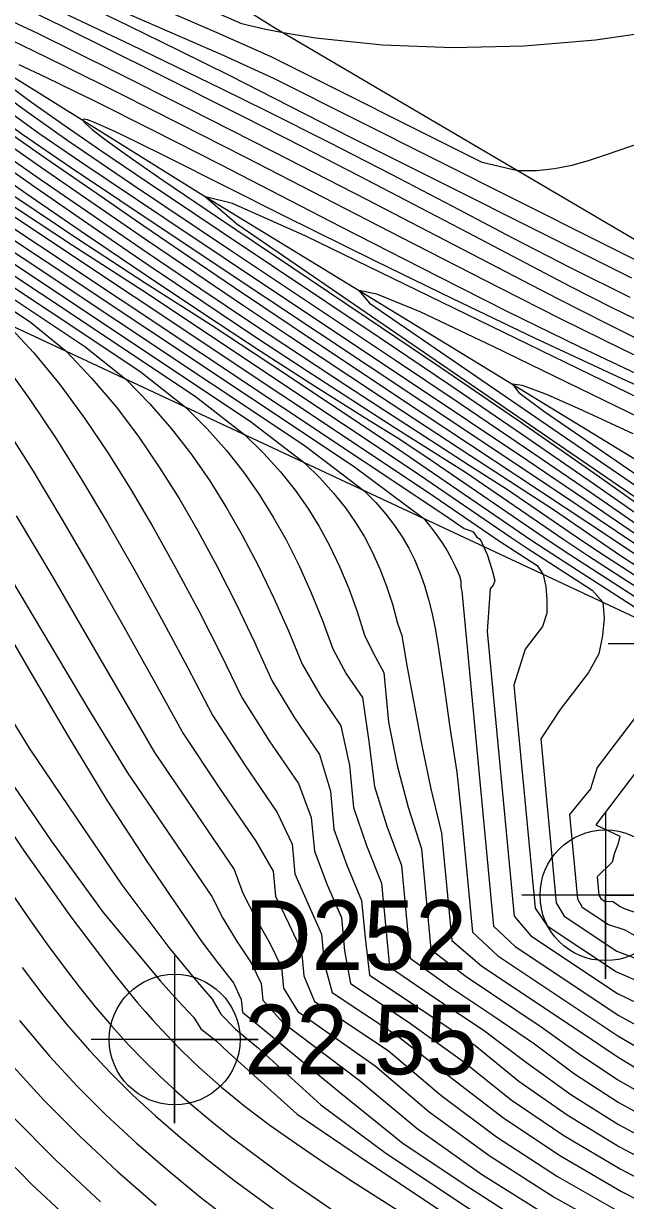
# Model space of a CAD drawing. Extents: x 2356077 to 2359823, y 225951 to 227822.
# Drawn here: x 2356709.45 to 2356731.04, y 227178.59 to 227220.81 of the extents above; entities that cross this region are included whole.
import ezdxf

# ---------------------------------------------------------------- set-up
doc = ezdxf.new("R2010")
doc.units = 0
for name, color, linetype in [('DTM Contours Major', 7, 'Continuous'), ('DTM Contours Minor', 7, 'Continuous'), ('Exist DTM Breakline', 7, 'Continuous'), ('Exist DTM Breakline Cogo Point CELL', 7, 'Continuous'), ('Exist DTM Regular Point CELL', 7, 'Continuous'), ('Exist DTM Regular Point Cogo Elevation', 7, 'Continuous'), ('Exist DTM Regular Point Cogo Number', 7, 'Continuous'), ('PH Exist DTM Breakline', 7, 'Continuous')]:
    doc.layers.add(name, color=color, linetype=linetype)

msp = doc.modelspace()

# ---------------------------------------------------------------- linework, layer by layer
at = {"layer": 'DTM Contours Major'}
for points in [[(2356697.999, 227222.074), (2356700.071, 227220.561), (2356702.169, 227219.049), (2356704.302, 227217.538), (2356706.479, 227216.026), (2356708.707, 227214.512), (2356711.208, 227212.858), (2356713.724, 227211.231), (2356720.925, 227206.443), (2356723.392, 227204.798), (2356726.934, 227202.371), (2356727.516, 227201.988), (2356729.842, 227200.486), (2356730.232, 227200.051), (2356730.279, 227199.475), (2356730.221, 227198.856), (2356730.084, 227198.2), (2356729.708, 227197.527), (2356728.702, 227196.203), (2356728, 227195.153), (2356728.559, 227189.267), (2356728.844, 227188.788), (2356730.726, 227187.535), (2356731.553, 227187.225)], [(2356701.503, 227221.717), (2356704.421, 227219.635), (2356707.31, 227217.594), (2356710.099, 227215.646), (2356712.021, 227214.316), (2356713.861, 227213.055), (2356715.63, 227211.853), (2356717.336, 227210.702), (2356718.989, 227209.596), (2356722.257, 227207.428), (2356725.455, 227205.328), (2356728.492, 227203.35), (2356730.025, 227202.3), (2356730.902, 227201.71), (2356734.234, 227199.558)], [(2356731.267, 227211.674), (2356721.187, 227216.729), (2356716.858, 227218.937), (2356715.043, 227219.84), (2356713.244, 227220.717), (2356711.454, 227221.577)], [(2356732.139, 227207.909), (2356729.416, 227209.203), (2356726.802, 227210.488), (2356724.323, 227211.735), (2356720.827, 227213.526), (2356716.529, 227215.742), (2356714.08, 227216.991), (2356711.989, 227218.037), (2356711.314, 227218.369), (2356710.265, 227218.878), (2356709.298, 227219.333)], [(2356708.714, 227218.744), (2356709.738, 227217.997), (2356710.944, 227217.147), (2356712.264, 227216.235), (2356713.887, 227215.131), (2356716.461, 227213.4), (2356722.201, 227209.559), (2356724.737, 227207.85), (2356727.311, 227206.098), (2356729.898, 227204.314), (2356732.471, 227202.508)], [(2356705.312, 227214.713), (2356717.581, 227206.554), (2356719.533, 227205.053), (2356720.087, 227204.502), (2356720.571, 227203.967), (2356720.993, 227203.441), (2356721.36, 227202.919), (2356721.679, 227202.394), (2356721.959, 227201.861), (2356722.231, 227201.255), (2356722.468, 227200.629), (2356722.678, 227199.978), (2356722.864, 227199.299), (2356723.024, 227198.862), (2356723.188, 227197.841), (2356723.733, 227194.91), (2356724.063, 227193.356), (2356724.444, 227191.77), (2356724.81, 227187.914), (2356725.885, 227186.997), (2356729.504, 227184.589), (2356730.775, 227183.728), (2356732.141, 227182.907)], [(2356708.834, 227210.055), (2356709.817, 227208.995), (2356710.749, 227207.859), (2356711.637, 227206.657), (2356712.486, 227205.399), (2356713.301, 227204.097), (2356714.088, 227202.759), (2356714.93, 227201.253), (2356715.744, 227199.725), (2356716.528, 227198.184), (2356717.282, 227196.637), (2356718.264, 227195.08), (2356719.31, 227193.547), (2356719.769, 227192.329), (2356719.884, 227191.118), (2356720.345, 227189.92), (2356720.854, 227188.744), (2356720.967, 227187.552), (2356721.181, 227186.369), (2356723.247, 227184.994), (2356725.239, 227183.562), (2356726.945, 227182.205), (2356728.824, 227180.923), (2356730.855, 227179.72), (2356733.018, 227178.595)], [(2356706.808, 227202.53), (2356709.623, 227197.665), (2356711.028, 227195.278), (2356712.439, 227192.956), (2356713.907, 227190.705), (2356715.848, 227187.864), (2356716.404, 227187.126), (2356716.976, 227186.404), (2356717.257, 227185.795), (2356717.3, 227185.341), (2356718.31, 227184.52), (2356720.825, 227182.44), (2356723.072, 227180.635), (2356725.493, 227179.017), (2356728.202, 227177.269)], [(2356709.402, 227186.951), (2356710.18, 227185.922), (2356710.979, 227184.93), (2356711.81, 227183.975), (2356712.566, 227183.171), (2356713.359, 227182.386), (2356714.194, 227181.615), (2356715.075, 227180.85), (2356716.007, 227180.086), (2356716.996, 227179.317), (2356719.032, 227177.826)]]:
    msp.add_lwpolyline(points, dxfattribs=at)
at = {"layer": 'DTM Contours Minor'}
for points in [[(2356675.565, 227239.487), (2356688.723, 227229.4), (2356689.261, 227228.93), (2356690.65, 227227.923), (2356691.684, 227227.129), (2356692.88, 227226.225), (2356697.895, 227222.574), (2356700.14, 227220.945), (2356702.376, 227219.334), (2356704.613, 227217.742), (2356706.862, 227216.167), (2356709.134, 227214.608), (2356711.469, 227213.044), (2356713.813, 227211.513), (2356716.138, 227210.032), (2356718.323, 227208.596), (2356722.824, 227205.597), (2356727.68, 227202.269), (2356729.317, 227201.207), (2356731.77, 227199.622)], [(2356675.054, 227229.772), (2356678.521, 227226.89), (2356681.448, 227223.752), (2356684.011, 227220.483), (2356688.753, 227214.079), (2356690.856, 227211.218), (2356692.64, 227208.461), (2356693.369, 227207.313), (2356694.719, 227205.162), (2356696.577, 227202.16), (2356699.99, 227196.632), (2356701.76, 227193.78), (2356702.834, 227192.065), (2356703.948, 227190.324), (2356705.11, 227188.579), (2356706.328, 227186.85), (2356707.608, 227185.161), (2356708.957, 227183.532), (2356710.191, 227182.178), (2356711.48, 227180.88), (2356712.822, 227179.631), (2356714.211, 227178.427)], [(2356736.072, 227207.936), (2356730.541, 227210.624), (2356729.085, 227211.366), (2356725.372, 227213.321), (2356723.451, 227214.325), (2356721.479, 227215.347), (2356719.453, 227216.388), (2356717.367, 227217.45), (2356714.199, 227219.041), (2356710.847, 227220.708), (2356709.227, 227221.495), (2356707.974, 227222.06), (2356697.238, 227227.105), (2356694.71, 227228.259), (2356694.083, 227228.263), (2356694.08, 227228.231), (2356695.667, 227226.882), (2356709.422, 227216.828), (2356711.101, 227215.687), (2356712.905, 227214.473), (2356716.283, 227212.214), (2356725.551, 227206.057), (2356729.331, 227203.536), (2356732.071, 227201.697)], [(2356732.263, 227209.1), (2356730.435, 227210.012), (2356728.615, 227210.943), (2356721.799, 227214.473), (2356718.415, 227216.212), (2356715.383, 227217.751), (2356712.713, 227219.089), (2356709.958, 227220.456), (2356704.772, 227222.89), (2356700.424, 227224.933), (2356698.91, 227225.553), (2356698.454, 227225.535), (2356699.216, 227224.754), (2356709.996, 227216.878), (2356711.545, 227215.826), (2356714.516, 227213.826), (2356718.739, 227211.009), (2356723.205, 227208.035), (2356725.372, 227206.585), (2356727.498, 227205.157), (2356729.582, 227203.749), (2356731.625, 227202.357)], [(2356732.451, 227220.577), (2356729.965, 227220.213), (2356727.408, 227220), (2356724.842, 227219.941), (2356722.325, 227220.037), (2356719.917, 227220.292), (2356719.334, 227220.381), (2356718.762, 227220.481), (2356718.136, 227220.604), (2356717.521, 227220.741), (2356717.275, 227220.805), (2356707.515, 227225.057)], [(2356732.053, 227216.692), (2356730.351, 227216.098), (2356729.733, 227215.895), (2356729.118, 227215.723), (2356728.494, 227215.597), (2356727.849, 227215.53), (2356727.171, 227215.534), (2356725.896, 227215.824), (2356718.305, 227219.632), (2356716.394, 227220.479), (2356710.754, 227222.935)], [(2356681.237, 227222.134), (2356683.269, 227219.385), (2356685.378, 227216.437), (2356687.487, 227213.416), (2356689.515, 227210.456), (2356691.378, 227207.687), (2356692.59, 227205.86), (2356693.704, 227204.157), (2356694.749, 227202.532), (2356695.464, 227201.406), (2356696.169, 227200.284), (2356697.582, 227198.006), (2356700.266, 227193.63), (2356701.555, 227191.569), (2356702.925, 227189.461), (2356704.38, 227187.347), (2356705.923, 227185.267), (2356707.556, 227183.261), (2356709.051, 227181.605), (2356710.605, 227180.031), (2356712.209, 227178.536)], [(2356701.453, 227222.201), (2356704.401, 227220.096), (2356707.374, 227217.995), (2356710.258, 227215.978), (2356712.051, 227214.737), (2356713.767, 227213.558), (2356715.42, 227212.431), (2356717.019, 227211.348), (2356720.1, 227209.279), (2356723.707, 227206.876), (2356727.175, 227204.58), (2356730.504, 227202.381), (2356731.445, 227201.741)], [(2356700.124, 227221.9), (2356702.572, 227220.132), (2356705.02, 227218.376), (2356707.454, 227216.646), (2356709.858, 227214.956), (2356711.907, 227213.536), (2356713.915, 227212.162), (2356715.875, 227210.837), (2356717.78, 227209.567), (2356719.621, 227208.355), (2356721.392, 227207.205), (2356722.743, 227206.338), (2356725.297, 227204.721), (2356728.829, 227202.3), (2356729.689, 227201.73), (2356733.811, 227199.067)], [(2356733.234, 227208.028), (2356730.946, 227209.122), (2356728.712, 227210.223), (2356726.546, 227211.316), (2356722.996, 227213.136), (2356717.42, 227216.005), (2356715.022, 227217.226), (2356712.962, 227218.263), (2356710.872, 227219.304), (2356709.816, 227219.826), (2356708.234, 227220.588), (2356705.153, 227222.036)], [(2356697.999, 227221.22), (2356699.889, 227219.893), (2356701.823, 227218.568), (2356703.633, 227217.313), (2356705.314, 227216.085), (2356707.087, 227214.8), (2356724.557, 227203.181), (2356725.256, 227202.702), (2356725.466, 227202.625), (2356725.577, 227202.574), (2356725.713, 227202.389), (2356725.823, 227202.317), (2356725.952, 227202.052), (2356726.073, 227201.763), (2356726.18, 227201.463), (2356726.274, 227201.151), (2356726.358, 227200.827), (2356726.289, 227200.662), (2356726.19, 227200.532), (2356726.083, 227198.999), (2356727.053, 227188.795), (2356727.641, 227188.084), (2356730.758, 227186.01), (2356731.847, 227185.485)], [(2356698, 227221.629), (2356699.972, 227220.201), (2356701.983, 227218.769), (2356704.043, 227217.331), (2356706.163, 227215.885), (2356708.144, 227214.52), (2356723.969, 227203.993), (2356726.14, 227202.505), (2356726.49, 227202.269), (2356727.878, 227201.372), (2356728.092, 227201.051), (2356728.18, 227200.62), (2356728.218, 227200.155), (2356728.216, 227199.658), (2356728.065, 227199.183), (2356727.444, 227198.365), (2356727.041, 227197.076), (2356727.801, 227189.077), (2356728.227, 227188.447), (2356730.713, 227186.792), (2356731.661, 227186.387)], [(2356700.189, 227221.392), (2356702.536, 227219.698), (2356704.877, 227218.019), (2356707.21, 227216.362), (2356709.533, 227214.734), (2356711.704, 227213.237), (2356713.845, 227211.783), (2356715.94, 227210.383), (2356717.97, 227209.051), (2356719.916, 227207.798), (2356721.76, 227206.637), (2356722.947, 227205.905), (2356724.112, 227205.123), (2356728.154, 227202.354), (2356729.046, 227201.764), (2356733.341, 227198.989)], [(2356701.486, 227221.269), (2356704.363, 227219.22), (2356707.178, 227217.234), (2356709.889, 227215.342), (2356711.947, 227213.922), (2356713.919, 227212.575), (2356715.811, 227211.294), (2356717.63, 227210.075), (2356719.382, 227208.912), (2356721.073, 227207.799), (2356722.574, 227206.819), (2356724.029, 227205.875), (2356725.439, 227204.969), (2356726.803, 227204.098), (2356729.47, 227202.27), (2356730.32, 227201.704), (2356734.354, 227199.098)], [(2356704.67, 227221.234), (2356709.553, 227217.665), (2356711.004, 227216.639), (2356713.36, 227215.04), (2356716.869, 227212.688), (2356722.753, 227208.76), (2356725.11, 227207.177), (2356727.456, 227205.59), (2356729.782, 227204.002), (2356732.078, 227202.414)], [(2356731.207, 227210.987), (2356729.09, 227212.037), (2356726.999, 227213.113), (2356724.851, 227214.25), (2356722.648, 227215.401), (2356720.415, 227216.547), (2356718.177, 227217.674), (2356716.551, 227218.476), (2356714.927, 227219.265), (2356713.298, 227220.047), (2356709.991, 227221.616)], [(2356733.03, 227211.517), (2356718.451, 227218.83), (2356716.624, 227219.668), (2356713.044, 227221.227)], [(2356711.628, 227177.418), (2356709.751, 227179.169), (2356707.915, 227181.033), (2356706.113, 227182.947), (2356704.202, 227185.43), (2356702.377, 227187.936), (2356700.671, 227190.469), (2356699.086, 227192.96), (2356697.626, 227195.343), (2356695.726, 227198.496), (2356694.648, 227200.26), (2356694.127, 227201.097), (2356693.611, 227201.913), (2356693.092, 227202.717), (2356692.345, 227203.848), (2356691.567, 227204.993), (2356690.742, 227206.177), (2356689.508, 227207.901), (2356688.186, 227209.709), (2356686.804, 227211.567), (2356685.395, 227213.442), (2356682.614, 227217.105), (2356680.51, 227219.871), (2356679.542, 227221.158)], [(2356698.01, 227220.857), (2356699.858, 227219.586), (2356701.518, 227218.393), (2356704.812, 227215.986), (2356706.531, 227214.747), (2356721.277, 227204.941), (2356723.813, 227203.052), (2356724.05, 227202.759), (2356724.266, 227202.469), (2356724.462, 227202.181), (2356724.639, 227201.894), (2356724.799, 227201.607), (2356724.944, 227201.318), (2356725.087, 227200.995), (2356725.129, 227200.826), (2356725.14, 227200.634), (2356725.152, 227200.54), (2356725.17, 227200.447), (2356726.312, 227188.429), (2356727.083, 227187.704), (2356730.802, 227185.229), (2356731.938, 227184.6)], [(2356734.078, 227206.636), (2356730.918, 227208.064), (2356727.815, 227209.513), (2356724.842, 227210.936), (2356722.074, 227212.289), (2356718.79, 227213.921), (2356714.601, 227216.025), (2356713.519, 227216.559), (2356712.728, 227216.938), (2356712.321, 227217.124), (2356711.99, 227217.265), (2356711.747, 227217.354), (2356711.602, 227217.384), (2356711.568, 227217.347), (2356711.67, 227217.223), (2356711.912, 227217.014), (2356712.281, 227216.729), (2356712.764, 227216.376), (2356713.348, 227215.962), (2356714.449, 227215.2), (2356716.407, 227213.871), (2356721.743, 227210.284), (2356724.415, 227208.476), (2356727.165, 227206.597), (2356729.91, 227204.691), (2356732.57, 227202.806)], [(2356702.314, 227215.017), (2356709.686, 227210.114), (2356710.974, 227209.055), (2356711.905, 227208.078), (2356712.767, 227207.058), (2356713.569, 227205.997), (2356714.319, 227204.9), (2356715.026, 227203.771), (2356715.699, 227202.614), (2356716.409, 227201.307), (2356717.088, 227199.974), (2356717.736, 227198.621), (2356718.354, 227197.251), (2356719.167, 227195.907), (2356720.069, 227194.587), (2356720.454, 227193.277), (2356720.584, 227191.913), (2356721.044, 227190.623), (2356721.571, 227189.358), (2356721.699, 227188.011), (2356721.861, 227186.668), (2356725.632, 227184.158), (2356727.216, 227182.871), (2356728.946, 227181.658), (2356730.822, 227180.52), (2356732.827, 227179.457)], [(2356703.064, 227214.941), (2356711.647, 227209.233), (2356713.114, 227208.054), (2356713.976, 227207.172), (2356714.759, 227206.271), (2356715.472, 227205.349), (2356716.126, 227204.408), (2356716.729, 227203.444), (2356717.292, 227202.458), (2356717.878, 227201.342), (2356718.429, 227200.199), (2356718.949, 227199.029), (2356719.441, 227197.834), (2356720.085, 227196.714), (2356720.832, 227195.619), (2356721.142, 227194.199), (2356721.286, 227192.686), (2356721.756, 227191.323), (2356722.287, 227189.98), (2356722.573, 227186.967), (2356724.239, 227185.837), (2356725.93, 227184.712), (2356727.492, 227183.538), (2356729.074, 227182.393), (2356730.795, 227181.32), (2356732.642, 227180.319)], [(2356703.816, 227214.863), (2356713.619, 227208.344), (2356715.254, 227207.054), (2356716.031, 227206.275), (2356716.725, 227205.495), (2356717.346, 227204.71), (2356717.903, 227203.917), (2356718.407, 227203.11), (2356718.868, 227202.287), (2356719.337, 227201.353), (2356719.771, 227200.391), (2356720.173, 227199.4), (2356720.549, 227198.379), (2356721.024, 227197.489), (2356721.608, 227196.634), (2356721.836, 227195.061), (2356722.039, 227193.442), (2356722.486, 227192.018), (2356723.003, 227190.604), (2356723.319, 227187.28), (2356724.773, 227186.234), (2356726.286, 227185.227), (2356727.775, 227184.208), (2356729.21, 227183.129), (2356730.777, 227182.121), (2356732.464, 227181.18)], [(2356704.571, 227214.783), (2356715.602, 227207.448), (2356717.393, 227206.053), (2356718.069, 227205.385), (2356718.663, 227204.728), (2356719.187, 227204.076), (2356719.648, 227203.423), (2356720.057, 227202.764), (2356720.423, 227202.092), (2356720.787, 227201.329), (2356721.115, 227200.54), (2356721.413, 227199.723), (2356721.685, 227198.873), (2356721.997, 227198.216), (2356722.376, 227197.537), (2356722.546, 227195.746), (2356722.853, 227194.193), (2356723.247, 227192.701), (2356723.721, 227191.211), (2356724.064, 227187.598), (2356725.322, 227186.62), (2356728.02, 227184.824), (2356729.356, 227183.868), (2356730.769, 227182.923), (2356732.296, 227182.043)], [(2356706.033, 227214.656), (2356719.511, 227205.693), (2356721.673, 227204.052), (2356722.083, 227203.625), (2356722.442, 227203.209), (2356722.755, 227202.802), (2356723.028, 227202.398), (2356723.264, 227201.994), (2356723.47, 227201.586), (2356723.666, 227201.124), (2356723.835, 227200.648), (2356723.979, 227200.155), (2356724.104, 227199.642), (2356724.214, 227199.106), (2356724.313, 227198.544), (2356724.523, 227197.109), (2356724.736, 227195.562), (2356724.993, 227193.951), (2356725.173, 227192.251), (2356725.557, 227188.211), (2356726.465, 227187.363), (2356730.768, 227184.499), (2356732.007, 227183.77)], [(2356735.989, 227205.2), (2356719.572, 227213.18), (2356716.943, 227214.361), (2356715.975, 227214.599), (2356717.095, 227213.634), (2356733.077, 227202.679)], [(2356735.926, 227204.543), (2356726.324, 227209.211), (2356723.671, 227210.472), (2356722.124, 227211.108), (2356721.478, 227211.236), (2356721.859, 227210.782), (2356733.976, 227202.472)], [(2356708.707, 227208.674), (2356709.678, 227207.329), (2356710.627, 227205.906), (2356711.554, 227204.424), (2356712.462, 227202.899), (2356713.443, 227201.186), (2356714.398, 227199.457), (2356715.326, 227197.724), (2356716.223, 227196), (2356717.37, 227194.237), (2356718.551, 227192.508), (2356719.085, 227191.368), (2356719.185, 227190.312), (2356719.653, 227189.218), (2356720.136, 227188.14), (2356720.234, 227187.1), (2356720.519, 227186.057), (2356722.826, 227184.522), (2356724.828, 227182.965), (2356726.677, 227181.538), (2356728.708, 227180.188), (2356730.895, 227178.918), (2356733.215, 227177.732)], [(2356731.314, 227206.098), (2356729.564, 227206.908), (2356728.238, 227207.488), (2356727.342, 227207.831), (2356726.982, 227207.874), (2356727.219, 227207.578), (2356728.107, 227206.906), (2356734.827, 227202.299)], [(2356708.747, 227206.421), (2356709.791, 227204.752), (2356710.825, 227203.033), (2356711.949, 227201.107), (2356713.052, 227199.172), (2356714.128, 227197.244), (2356715.176, 227195.342), (2356716.483, 227193.385), (2356717.786, 227191.478), (2356718.401, 227190.4), (2356718.486, 227189.506), (2356718.968, 227188.518), (2356719.417, 227187.544), (2356719.501, 227186.653), (2356719.882, 227185.73), (2356722.525, 227183.97), (2356724.415, 227182.368), (2356726.413, 227180.87), (2356728.596, 227179.45), (2356730.939, 227178.114)], [(2356709.189, 227203.152), (2356710.46, 227201.009), (2356711.712, 227198.865), (2356714.144, 227194.662), (2356717.006, 227190.468), (2356717.319, 227189.61), (2356717.787, 227188.702), (2356718.289, 227187.819), (2356718.697, 227186.956), (2356718.768, 227186.212), (2356719.284, 227185.376), (2356722.067, 227183.415), (2356723.999, 227181.771), (2356726.149, 227180.2), (2356728.487, 227178.709), (2356730.986, 227177.307)], [(2356709.019, 227200.852), (2356711.791, 227196.194), (2356713.173, 227193.931), (2356716.201, 227189.497), (2356716.596, 227188.719), (2356717.087, 227187.91), (2356717.617, 227187.121), (2356717.977, 227186.373), (2356718.034, 227185.774), (2356718.749, 227184.98), (2356721.482, 227182.902), (2356723.571, 227181.177), (2356725.879, 227179.529), (2356728.374, 227177.967)], [(2356708.107, 227197.317), (2356709.652, 227194.815), (2356711.345, 227192.306), (2356712.975, 227189.919), (2356714.66, 227187.67), (2356715.172, 227187.039), (2356715.692, 227186.42), (2356716.221, 227185.813), (2356716.531, 227185.27), (2356717.049, 227184.736), (2356717.877, 227184.056), (2356720.118, 227182.025), (2356722.447, 227180.293), (2356728.056, 227176.56)], [(2356731.347, 227195.868), (2356730.023, 227194.124), (2356729.788, 227193.355), (2356729.033, 227192.438), (2356729.321, 227189.409), (2356729.491, 227189.109), (2356730.427, 227188.486), (2356731.012, 227188.297), (2356731.514, 227188.011)], [(2356732.197, 227195.001), (2356729.972, 227192.071), (2356730.833, 227191.657), (2356730.767, 227191.361), (2356730.65, 227191.045), (2356730.564, 227190.724), (2356730.021, 227190.202), (2356730.084, 227189.539), (2356730.155, 227189.419), (2356730.286, 227189.332), (2356730.584, 227189.321), (2356730.716, 227189.23), (2356730.852, 227189.143), (2356730.993, 227189.061), (2356732.195, 227188.65), (2356732.454, 227188.866), (2356732.774, 227188.922), (2356733.035, 227189.072), (2356736.145, 227186.908), (2356732.197, 227195.001)], [(2356708.603, 227194.17), (2356710.435, 227191.488), (2356712.311, 227188.921), (2356714.364, 227186.453), (2356714.756, 227186.016), (2356715.152, 227185.584), (2356715.554, 227185.157), (2356715.805, 227184.754), (2356716.345, 227184.33), (2356716.795, 227183.906), (2356719.266, 227181.691), (2356721.803, 227179.97), (2356727.804, 227175.976)], [(2356707.752, 227193.679), (2356709.473, 227191.125), (2356711.141, 227188.767), (2356712.719, 227186.688), (2356713.272, 227186.008), (2356713.543, 227185.685), (2356713.812, 227185.372), (2356714.079, 227185.07), (2356714.575, 227184.53), (2356715.037, 227184.054), (2356715.502, 227183.6), (2356715.737, 227183.379), (2356716.552, 227182.658), (2356717.4, 227181.968), (2356718.289, 227181.296), (2356719.226, 227180.629), (2356720.217, 227179.957), (2356721.271, 227179.265), (2356723.115, 227178.088)], [(2356708.351, 227190.568), (2356709.695, 227188.622), (2356710.286, 227187.795), (2356710.867, 227187.009), (2356711.443, 227186.259), (2356712.022, 227185.54), (2356712.612, 227184.849), (2356713.219, 227184.18), (2356713.767, 227183.613), (2356714.338, 227183.055), (2356714.936, 227182.503), (2356715.566, 227181.952), (2356716.23, 227181.398), (2356716.934, 227180.836), (2356719.033, 227179.275), (2356721.383, 227177.665)], [(2356709.302, 227185.044), (2356710.382, 227183.766), (2356711.368, 227182.697), (2356712.401, 227181.663), (2356713.485, 227180.657), (2356714.62, 227179.673), (2356715.809, 227178.703), (2356717.056, 227177.741)]]:
    msp.add_lwpolyline(points, dxfattribs=at)
at = {"layer": 'Exist DTM Breakline'}
msp.add_lwpolyline([(2356613.053, 227270.361), (2356650.333, 227243.926), (2356697.977, 227215.131), (2356733.42, 227198.56), (2356756.55, 227184.242), (2356802.729, 227156.081), (2356830.777, 227139.335)], dxfattribs=at)
at = {"layer": 'Exist DTM Breakline Cogo Point CELL'}
msp.add_lwpolyline([(2356733.42, 227201.56), (2356733.42, 227195.56), (2356733.42, 227198.56), (2356736.42, 227198.56), (2356730.42, 227198.56)], dxfattribs=at)
at = {"layer": 'Exist DTM Regular Point CELL'}
for points in [[(2356730.319, 227192.538), (2356730.319, 227186.538), (2356730.319, 227189.538), (2356733.319, 227189.538), (2356727.319, 227189.538)], [(2356714.87, 227187.364), (2356714.87, 227181.364), (2356714.87, 227184.364), (2356717.87, 227184.364), (2356711.87, 227184.364)]]:
    msp.add_lwpolyline(points, dxfattribs=at)
for centre in [(2356730.319, 227189.538), (2356714.87, 227184.364)]:
    msp.add_circle(centre, 2.344, dxfattribs=at)
at = {"layer": 'PH Exist DTM Breakline'}
for points in [[(2356874.006, 227127.776), (2356827.187, 227157.253), (2356798.45, 227174.201), (2356773.903, 227189.099), (2356754.358, 227199.973), (2356736.653, 227209.957), (2356718.488, 227220.641), (2356700.429, 227231.907), (2356681.257, 227242.915), (2356663.176, 227254.535), (2356644.166, 227266.793), (2356622.923, 227279.772), (2356610.333, 227287.071), (2356602.922, 227291.069), (2356601.494, 227294.51)], [(2356595.251, 227285.48), (2356610.292, 227279.585), (2356630.224, 227267.853), (2356651.648, 227254.925), (2356672.172, 227242.038), (2356694.087, 227228.261), (2356715.804, 227214.703), (2356738.018, 227201.132), (2356760.194, 227188.688), (2356783.837, 227175.884), (2356808.534, 227162.068)]]:
    msp.add_lwpolyline(points, dxfattribs=at)

# ---------------------------------------------------------------- texts
at = {"layer": 'Exist DTM Regular Point Cogo Elevation'}
msp.add_text('22.55', height=2.5, dxfattribs=at).set_placement((2356717.37, 227183.114))
at = {"layer": 'Exist DTM Regular Point Cogo Number'}
msp.add_text('D252', height=2.5, dxfattribs=at).set_placement((2356717.37, 227186.864))

doc.saveas('drawing.dxf')
